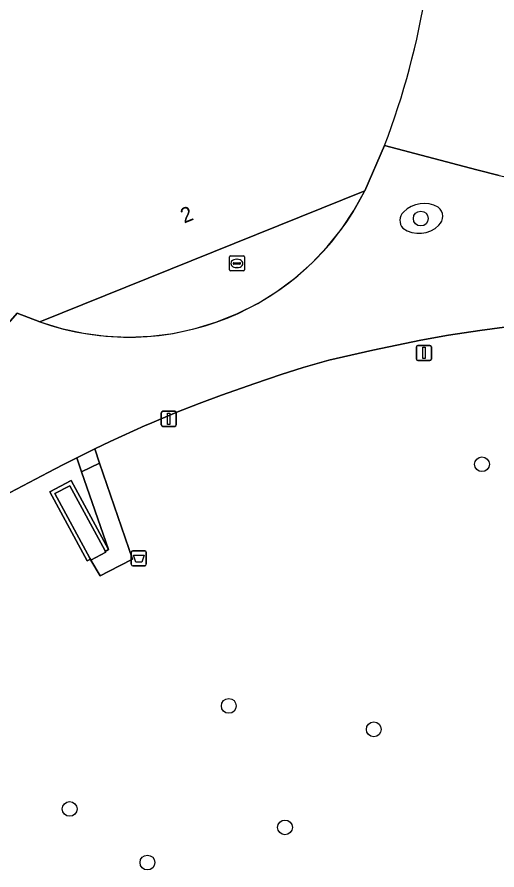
# Model space of a CAD drawing. Extents: x 161477 to 163040, y 383680 to 384871.
# Drawn here: x 161587.6 to 161619.3, y 384025.4 to 384081.8 of the extents above; entities that cross this region are included whole.
import ezdxf

# ---------------------------------------------------------------- set-up
doc = ezdxf.new("R2010")
doc.units = 0
for name, color, linetype in [('IMGEO_Afvalbak', 7, 'Continuous'), ('IMGEO_Boom', 7, 'Continuous'), ('IMGEO_Fietspad_gesloten', 7, 'Continuous'), ('IMGEO_Groenvoorziening', 7, 'Continuous'), ('IMGEO_Lichtmast', 7, 'Continuous'), ('IMGEO_Muur', 7, 'Continuous'), ('IMGEO_Pand', 7, 'Continuous'), ('IMGEO_Pand_nummerreeks', 7, 'Continuous'), ('IMGEO_Pand_overbouw', 7, 'Continuous'), ('IMGEO_Rijbaan_lokaal_gesloten', 7, 'Continuous'), ('IMGEO_Rioolput', 7, 'Continuous'), ('IMGEO_Terreindeel_open', 7, 'Continuous'), ('IMGEO_Voetpad_gesloten', 7, 'Continuous'), ('IMGEO_Voetpad_op_trap', 7, 'Continuous'), ('IMGEO_Voetpad_open', 7, 'Continuous')]:
    doc.layers.add(name, color=color, linetype=linetype)

msp = doc.modelspace()

# ---------------------------------------------------------------- linework, layer by layer
at = {"layer": 'IMGEO_Afvalbak'}
for p, q in [((161595.135, 384045.65), (161595.135, 384046.45)), ((161595.135, 384046.45), (161595.135, 384045.65)), ((161595.235, 384046.55), (161596.025, 384046.55)), ((161596.025, 384046.55), (161595.235, 384046.55)), ((161596.125, 384046.45), (161596.125, 384045.65)), ((161596.125, 384045.65), (161596.125, 384046.45)), ((161596.025, 384045.55), (161595.235, 384045.55)), ((161595.235, 384045.55), (161596.025, 384045.55))]:
    msp.add_line(p, q, dxfattribs=at)
msp.add_lwpolyline([(161595.278, 384046.264), (161595.982, 384046.264), (161595.833, 384045.794), (161595.427, 384045.794), (161595.278, 384046.264)], dxfattribs=at)
for centre, start, end in [((161595.235, 384046.45), 90, 180), ((161595.235, 384046.45), 90, 180), ((161596.025, 384046.45), 0, 90), ((161596.025, 384046.45), 360, 90), ((161595.235, 384045.65), 180, 270), ((161595.235, 384045.65), 180, 270), ((161596.025, 384045.65), 270, 0), ((161596.025, 384045.65), 270, 0)]:
    msp.add_arc(centre, 0.1, start, end, dxfattribs=at)
at = {"layer": 'IMGEO_Boom'}
for centre in [(161614.254, 384068.507), (161618.293, 384052.264), (161601.575, 384036.292), (161611.151, 384034.742), (161591.063, 384029.482), (161605.282, 384028.259), (161596.201, 384025.937)]:
    msp.add_circle(centre, 0.489, dxfattribs=at)
at = {"layer": 'IMGEO_Fietspad_gesloten'}
msp.add_lwpolyline([(161610.554, 384070.34), (161589.095, 384061.681)], dxfattribs=at)
msp.add_arc((161594.952, 384078.085), 17.418, 250.3499, 333.5996, dxfattribs=at)
at = {"layer": 'IMGEO_Groenvoorziening'}
for points in [[(161611.855, 384073.331), (161617.96, 384071.728), (161619.424, 384071.346), (161620.128, 384071.199), (161622.616, 384070.767), (161624.228, 384070.531), (161625.235, 384070.412), (161626.195, 384070.341), (161627.968, 384070.283), (161629.256, 384070.276)], [(161619.78, 384061.327), (161618.151, 384061.1), (161616.078, 384060.791), (161614.264, 384060.475), (161611.077, 384059.816), (161608.187, 384059.136), (161606.487, 384058.661), (161605.028, 384058.197), (161603.293, 384057.612), (161601.089, 384056.836), (161599.611, 384056.29), (161598.152, 384055.712), (161596.336, 384054.942), (161596.047, 384054.816), (161593.749, 384053.774), (161592.72, 384053.274), (161593.039, 384052.347), (161595.22, 384046.001), (161593.62, 384045.173), (161593.075, 384044.89), (161592.466, 384045.93), (161592.434, 384045.989), (161592.226, 384045.875), (161589.758, 384050.442), (161591.166, 384051.189), (161593.628, 384046.621), (161591.849, 384051.757), (161591.527, 384052.688), (161590.615, 384052.22), (161589.643, 384051.721), (161587.142, 384050.391)]]:
    msp.add_lwpolyline(points, dxfattribs=at)
msp.add_arc((161563.415, 384091.819), 51.849, 339.1097, 350.937, dxfattribs=at)
at = {"layer": 'IMGEO_Lichtmast'}
for p, q in [((161613.965, 384059.22), (161613.965, 384060.02)), ((161613.965, 384060.02), (161613.965, 384059.22)), ((161614.065, 384060.12), (161614.855, 384060.12)), ((161614.855, 384060.12), (161614.065, 384060.12)), ((161614.955, 384060.02), (161614.955, 384059.22)), ((161614.955, 384059.22), (161614.955, 384060.02)), ((161614.855, 384059.12), (161614.065, 384059.12)), ((161614.065, 384059.12), (161614.855, 384059.12)), ((161597.115, 384054.87), (161597.115, 384055.67)), ((161597.115, 384055.67), (161597.115, 384054.87)), ((161597.215, 384055.77), (161598.005, 384055.77)), ((161598.005, 384055.77), (161597.215, 384055.77)), ((161598.105, 384055.67), (161598.105, 384054.87)), ((161598.105, 384054.87), (161598.105, 384055.67)), ((161598.005, 384054.77), (161597.215, 384054.77)), ((161597.215, 384054.77), (161598.005, 384054.77))]:
    msp.add_line(p, q, dxfattribs=at)
for points in [[(161614.385, 384059.995), (161614.535, 384059.995), (161614.535, 384059.245), (161614.385, 384059.245), (161614.385, 384059.995)], [(161597.535, 384055.645), (161597.685, 384055.645), (161597.685, 384054.895), (161597.535, 384054.895), (161597.535, 384055.645)]]:
    msp.add_lwpolyline(points, dxfattribs=at)
for centre, start, end in [((161614.065, 384060.02), 90, 180), ((161614.065, 384060.02), 90, 180), ((161614.855, 384060.02), 0, 90), ((161614.855, 384060.02), 360, 90), ((161614.065, 384059.22), 180, 270), ((161614.065, 384059.22), 180, 270), ((161614.855, 384059.22), 270, 0), ((161614.855, 384059.22), 270, 0), ((161597.215, 384055.67), 90, 180), ((161597.215, 384055.67), 90, 180), ((161598.005, 384055.67), 0, 90), ((161598.005, 384055.67), 360, 90), ((161597.215, 384054.87), 180, 270), ((161597.215, 384054.87), 180, 270), ((161598.005, 384054.87), 270, 0), ((161598.005, 384054.87), 270, 0)]:
    msp.add_arc(centre, 0.1, start, end, dxfattribs=at)
at = {"layer": 'IMGEO_Muur'}
msp.add_lwpolyline([(161591.067, 384050.847), (161593.378, 384046.578), (161593.416, 384046.507), (161593.628, 384046.621), (161591.166, 384051.189), (161589.758, 384050.442), (161592.226, 384045.875), (161592.434, 384045.989), (161592.399, 384046.053), (161590.091, 384050.329)], close=True, dxfattribs=at)
at = {"layer": 'IMGEO_Pand'}
msp.add_lwpolyline([(161587.591, 384062.259), (161589.095, 384061.681), (161610.554, 384070.34), (161611.855, 384073.331)], dxfattribs=at)
msp.add_arc((161563.415, 384091.819), 51.849, 339.1097, 350.937, dxfattribs=at)
at = {"layer": 'IMGEO_Pand_overbouw'}
msp.add_lwpolyline([(161610.554, 384070.34), (161589.095, 384061.681), (161590.517, 384061.241), (161591.971, 384060.924), (161593.447, 384060.732), (161594.933, 384060.667), (161596.42, 384060.729), (161597.897, 384060.918), (161599.351, 384061.232), (161600.774, 384061.669), (161602.154, 384062.226), (161603.482, 384062.898), (161604.747, 384063.682), (161605.941, 384064.57), (161607.054, 384065.558), (161608.08, 384066.637), (161609.009, 384067.799), (161609.836, 384069.036)], close=True, dxfattribs=at)
at = {"layer": 'IMGEO_Rijbaan_lokaal_gesloten'}
msp.add_lwpolyline([(161585.442, 384059.817), (161587.591, 384062.259)], dxfattribs=at)
at = {"layer": 'IMGEO_Rioolput'}
for p, q in [((161601.684, 384066.04), (161602.536, 384066.04)), ((161601.609, 384065.114), (161601.609, 384065.966)), ((161601.868, 384065.534), (161601.868, 384065.546)), ((161602.306, 384065.497), (161601.908, 384065.497)), ((161601.911, 384065.583), (161602.309, 384065.583)), ((161602.097, 384065.82), (161602.122, 384065.82)), ((161602.352, 384065.546), (161602.352, 384065.534)), ((161602.61, 384065.966), (161602.61, 384065.114)), ((161602.536, 384065.04), (161601.684, 384065.04)), ((161602.12, 384065.26), (161602.095, 384065.26))]:
    msp.add_line(p, q, dxfattribs=at)
for points in [[(161601.684, 384066.04), (161602.536, 384066.04)], [(161601.609, 384065.114), (161601.609, 384065.966)], [(161602.61, 384065.966), (161602.61, 384065.114)], [(161602.536, 384065.04), (161601.684, 384065.04)]]:
    msp.add_lwpolyline(points, dxfattribs=at)
for centre, radius, start, end in [((161601.686, 384065.964), 0.0765, 91.552, 178.448), ((161601.686, 384065.964), 0.0765, 91.552, 178.448), ((161602.534, 384065.964), 0.0765, 1.552, 88.448), ((161602.534, 384065.964), 0.0765, 1.552, 88.448), ((161601.908, 384065.543), 0.0403, 85.8775, 175.7526), ((161601.905, 384065.533), 0.0366, 178.938, 274.7102), ((161602.309, 384065.54), 0.043, 264.8664, 352.4533), ((161602.313, 384065.545), 0.0386, 1.7309, 96.639), ((161601.686, 384065.116), 0.0765, 181.552, 268.448), ((161601.686, 384065.116), 0.0765, 181.552, 268.448), ((161602.534, 384065.116), 0.0765, 271.552, 358.448), ((161602.534, 384065.116), 0.0765, 271.552, 358.448)]:
    msp.add_arc(centre, radius, start, end, dxfattribs=at)
for centre, major_axis, ratio, start_param, end_param in [((161602.096, 384065.54), (-0.387, 0.002), 0.722429, 4.712389, 7.853982), ((161602.121, 384065.54), (-0.39, 0.002), 0.717154, 1.570796, 4.712389)]:
    msp.add_ellipse(centre, major_axis=major_axis, ratio=ratio, start_param=start_param, end_param=end_param, dxfattribs=at)
at = {"layer": 'IMGEO_Terreindeel_open'}
for centre, radius, start, end in [((161614.46, 384067.631), 1.875, 59.7268, 136.0507), ((161613.63, 384068.383), 0.756, 133.4171, 222.8112), ((161614.955, 384068.644), 0.755, 310.7162, 53.3677), ((161614.141, 384069.376), 1.846, 234.7361, 315.047)]:
    msp.add_arc(centre, radius, start, end, dxfattribs=at)
at = {"layer": 'IMGEO_Voetpad_gesloten'}
for points in [[(161619.424, 384071.346), (161617.96, 384071.728), (161611.855, 384073.331), (161610.554, 384070.34)], [(161589.095, 384061.681), (161587.591, 384062.259), (161585.442, 384059.817)], [(161587.142, 384050.391), (161589.643, 384051.721), (161590.615, 384052.22), (161591.527, 384052.688), (161592.72, 384053.274), (161593.749, 384053.774), (161596.047, 384054.816), (161596.336, 384054.942), (161598.152, 384055.712), (161599.611, 384056.29), (161601.089, 384056.836), (161603.293, 384057.612), (161605.028, 384058.197), (161606.487, 384058.661), (161608.187, 384059.136), (161611.077, 384059.816), (161614.264, 384060.475), (161616.078, 384060.791), (161618.151, 384061.1), (161619.78, 384061.327)]]:
    msp.add_lwpolyline(points, dxfattribs=at)
for centre, radius, start, end in [((161594.952, 384078.085), 17.418, 250.3499, 333.5996), ((161614.46, 384067.631), 1.875, 59.7268, 136.0507), ((161613.63, 384068.383), 0.756, 133.4171, 222.8112), ((161614.955, 384068.644), 0.755, 310.7162, 53.3677), ((161614.141, 384069.376), 1.846, 234.7361, 315.047)]:
    msp.add_arc(centre, radius, start, end, dxfattribs=at)
at = {"layer": 'IMGEO_Voetpad_op_trap'}
for points in [[(161592.72, 384053.274), (161591.527, 384052.688), (161591.849, 384051.757), (161593.039, 384052.347)], [(161591.067, 384050.847), (161590.091, 384050.329), (161592.399, 384046.053), (161592.434, 384045.989), (161592.466, 384045.93), (161593.446, 384046.451), (161593.416, 384046.507), (161593.378, 384046.578)]]:
    msp.add_lwpolyline(points, close=True, dxfattribs=at)
at = {"layer": 'IMGEO_Voetpad_open'}
msp.add_lwpolyline([(161593.039, 384052.347), (161591.849, 384051.757), (161593.628, 384046.621), (161593.416, 384046.507), (161593.446, 384046.451), (161592.466, 384045.93), (161593.075, 384044.89), (161593.62, 384045.173), (161595.22, 384046.001)], close=True, dxfattribs=at)

# ---------------------------------------------------------------- texts
at = {"layer": 'IMGEO_Pand_nummerreeks'}
msp.add_text('2', height=1, rotation=21.738, dxfattribs=at).set_placement((161598.626, 384068.174))

doc.saveas('drawing.dxf')
